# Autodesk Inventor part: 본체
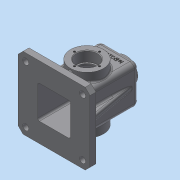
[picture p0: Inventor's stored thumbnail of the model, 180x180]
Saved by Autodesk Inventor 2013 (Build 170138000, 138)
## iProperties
Created: 2018-10
Part Number: 본체
Material: 일반
Document SubType Name: Modeling
Designer: Administrator
Density: 1 g/cm^3
Author: Administrator
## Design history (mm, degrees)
sketch "스케치1"
  geometry: L1 (-55, 32.5)-(55, 32.5); L2 (55, 32.5)-(55, -32.5); L3 (55, -32.5)-(-55, -32.5); L4 (-55, -32.5)-(-55, 32.5); L5 (-55, 32.5)-(55, -32.5); L6 (55, 32.5)-(-55, -32.5); 1 further point
  constraints: 12 end point, 2 midpoint, 2 parallel, 1 horizontal, 1 perpendicular
  dimensions: "d0" = 110 distance of L2.end L3.end; "d1" = 65 distance of L1.end L2.end
extrude "돌출1" new body sketch "스케치1" stored distance "d2" = 65; taper "d3" = 0 deg
fillet "모깎기1" dims "d4" = 8
fillet "모깎기2" dims "d5" = 8
feature "쉘1" dims "d6" = 5
sketch "스케치2"
  geometry: L1 (57, -8)-(57, -57) reference; L2 (0, 0)-(49, 0) reference; L3 (-8, -57)-(-8, -8) reference; L4 (49, -65)-(0, -65) reference; L5 (-35.5, -92.5)-(84.5, -92.5); L6 (84.5, -92.5)-(84.5, 27.5); L7 (84.5, 27.5)-(-35.5, 27.5); L8 (-35.5, 27.5)-(-35.5, -92.5); L9 (-35.5, -92.5)-(84.5, 27.5); L10 (84.5, -92.5)-(-35.5, 27.5); A1 r 8 centre (49, -57) between (49, -65) and (57, -57) reference; A2 r 8 centre (49, -8) between (57, -8) and (49, 0) reference; A3 r 8 centre (0, -8) between (0, 0) and (-8, -8) reference; A4 r 8 centre (0, -57) between (-8, -57) and (0, -65) reference; 1 further point
  constraints: 12 end point, 2 midpoint, 2 parallel, 1 horizontal, 1 perpendicular
  dimensions: "d7" = 120 distance of L7.end L6.end; "d8" = 120 distance of L6.end L5.end
extrude "돌출2" join sketch "스케치2" distance "d9" = 10; taper "d10" = 0 deg
chamfer "모따기1" distance "d11" = 8; stored, may be unused: second distance "d12" = 2, angle "d13" = 45 deg
sketch "스케치3"
  geometry: L1 (48, -45)-(35.218, 27.493); L2 (-24.5, 55)-(24.5, 55) reference; L3 (32.5, 47)-(32.5, -45) reference; L4 (32.5, -45)-(60, -45) reference; L5 (60, -45)-(60, -55) reference; L6 (60, -55)-(27.5, -55) reference; L7 (27.5, -55)-(27.5, 47) reference; L8 (24.5, 50)-(-24.5, 50) reference; L9 (-27.5, 47)-(-27.5, -55) reference; L10 (-27.5, -55)-(-60, -55) reference; L11 (-60, -55)-(-60, -45) reference; L12 (-60, -45)-(-32.5, -45) reference; L13 (-32.5, -45)-(-32.5, 47) reference; A1 r 8 centre (-24.5, 47) between (-24.5, 55) and (-32.5, 47) reference; A2 r 8 centre (24.5, 47) between (32.5, 47) and (24.5, 55) reference; A3 r 3 centre (24.5, 47) between (27.5, 47) and (24.5, 50) reference; A4 r 3 centre (-24.5, 47) between (-24.5, 50) and (-27.5, 47) reference; 1 further point
  constraints: 2 end point, 1 point on line
  dimensions: "d14" = 12 distance from line of L5 L1.start; "d15" = 10 deg angle of L5 L1
feature "리브1" sketch "스케치3" dims "d16" = 1, "d17" = 10, "d18" = 0, "d19" = 0, "d20" = 1, "d21" = 1
fillet "모깎기3" dims "d22" = 3
fillet "모깎기4" dims "d23" = 3
node "작업 평면1"
sketch "스케치4"
  geometry: C1 r 27.5 at (24.5, -47); 1 further point
  constraints: 1 centre point, 1 coincident
  dimensions: "d26" = 55 diameter of C1
extrude "돌출3" join sketch "스케치4" stored distance "d27" = 10; taper "d28" = 0 deg
hole "구멍1" diameter "d31" = 30; stored, may be unused: countersink angle "d35" = 90 deg, drill point angle "d37" = 118 deg; dims "d29" = 10, "d30" = 10, "d32" = 6, "d33" = 35, "d34" = 17, "d36" = 20
fillet "모깎기6" dims "d38" = 0.3
chamfer "모따기2" distance "d39" = 1; stored, may be unused: second distance "d40" = 2, angle "d41" = 45 deg
sketch "스케치5"
  geometry: L1 (0, 0)-(0, 21); C1 r 18.5 at (0, 0) reference
  constraints: 2 end point, 1 vertical
  dimensions: "d42" = 21 distance of L1.start L1.end
hole "구멍2" sketch "스케치5" at (0, 21) diameter "d43" = 3.459; stored, may be unused: countersink angle "d47" = 90 deg, drill point angle "d49" = 118 deg; dims "d44" = 8, "d45" = 35, "d46" = 17, "d48" = 10
sketch "스케치6"
  geometry: L1 (-55, 27.5)-(-55, 60) reference; L2 (-55, 60)-(-45, 60) reference; L3 (-45, 60)-(-45, 32.5) reference; L4 (-45, 32.5)-(-27.5, 32.5) reference; L5 (-27.5, 32.5)-(-27.5, 47.5) reference; L6 (-27.5, 47.5)-(-22.73, 47.5) reference; L7 (-22.73, 47.5)-(-22.73, 37.5) reference; L8 (-22.73, 37.5)-(-21, 36.461) reference; L9 (-21, 36.461)-(-19.271, 37.5) reference; L10 (-19.271, 37.5)-(-19.271, 47.5) reference; L11 (-19.271, 47.5)-(-18.5, 47.5) reference; L12 (-18.5, 47.5)-(-17.5, 46.5) reference; L13 (-17.5, 46.5)-(-17.5, 30.8) reference; L14 (-17.2, 30.5)-(-15, 30.5) reference; L15 (-15, 30.5)-(-15, 27.5) reference; L16 (-15, 27.5)-(-55, 27.5) reference; L17 (50, -24.5)-(50, 24.5) reference; L18 (47, 27.5)-(15, 27.5) reference; L19 (15, 27.5)-(15, 30.5) reference; L20 (15, 30.5)-(17.2, 30.5) reference; L21 (17.5, 30.8)-(17.5, 46.5) reference; L22 (17.5, 46.5)-(18.5, 47.5) reference; L23 (18.5, 47.5)-(19.271, 47.5) reference; L24 (19.271, 47.5)-(19.271, 37.5) reference; L25 (19.271, 37.5)-(21, 36.461) reference; L26 (21, 36.461)-(22.73, 37.5) reference; L27 (22.73, 37.5)-(22.73, 47.5) reference; L28 (22.73, 47.5)-(27.5, 47.5) reference; L29 (27.5, 47.5)-(27.5, 32.5) reference; L30 (27.5, 32.5)-(47, 32.5) reference; L31 (55, 24.5)-(55, -24.5) reference; L32 (47, -32.5)-(-45, -32.5) reference; L33 (-45, -32.5)-(-45, -60) reference; L34 (-45, -60)-(-55, -60) reference; L35 (-55, -60)-(-55, -27.5) reference; L36 (-55, -27.5)-(47, -27.5) reference; L37 (-45, 42.5)-(-31.143, 42.5); A1 r 0.3 centre (-17.2, 30.8) between (-17.5, 30.8) and (-17.2, 30.5) reference; A2 r 3 centre (47, 24.5) between (50, 24.5) and (47, 27.5) reference; A3 r 0.3 centre (17.2, 30.8) between (17.2, 30.5) and (17.5, 30.8) reference; A4 r 8 centre (47, 24.5) between (55, 24.5) and (47, 32.5) reference; A5 r 8 centre (47, -24.5) between (47, -32.5) and (55, -24.5) reference; A6 r 3 centre (47, -24.5) between (47, -27.5) and (50, -24.5) reference; 1 further point
  constraints: 2 end point, 1 parallel, 1 point on line
  dimensions: "d53" = 15 distance between parallel lines of L16 L37
feature "리브2" sketch "스케치6" dims "d54" = 1, "d55" = 6, "d56" = 0, "d57" = 0, "d58" = 1, "d59" = 1
fillet "모깎기7" dims "d60" = 3
fillet "모깎기9" dims "d62" = 3
fillet "모깎기10" dims "d63" = 3
fillet "모깎기11" dims "d64" = 1
fillet "모깎기12" dims "d65" = 3
node "작업 평면2"
sketch "스케치7"
  geometry: C1 r 20 at (0, 0); 1 further point
  constraints: 1 centre point, 1 coincident
  dimensions: "d67" = 40 diameter of C1
extrude "돌출4" join sketch "스케치7" stored distance "d68" = 10; taper "d69" = 7 deg
fillet "모깎기13" dims "d70" = 3
hole "구멍3" diameter "d73" = 22.835; stored, may be unused: countersink angle "d77" = 90 deg, drill point angle "d79" = 0 deg; dims "d71" = 10, "d72" = 10, "d74" = 20, "d75" = 35, "d76" = 17, "d78" = 10
chamfer "모따기3" distance "d80" = 1; stored, may be unused: second distance "d81" = 2, angle "d82" = 45 deg
sketch "스케치8"
  geometry: 2 further points
  dimensions: "d83" = 47.5 horizontal distance of point (4.5, -12.5) point (52, -60); "d84" = 47.5 horizontal distance of point (4.5, -12.5) point (52, -60)
hole "구멍4" sketch "스케치8" at (4.5, -12.5) diameter "d85" = 10; stored, may be unused: countersink angle "d89" = 90 deg, drill point angle "d91" = 0 deg; dims "d86" = 20, "d87" = 35, "d88" = 17, "d90" = 10
sketch "스케치9"
  geometry: L1 (-8, 0)-(-8, -91) reference; L2 (4.5, 18)-(44.5, 18) reference; 1 further point
  constraints: 1 other
  dimensions: "d98" = 32.5 distance from line of point (24.5, -8) L1; "d99" = 26 distance from line of L2 point (24.5, -8)
feature "엠보싱1" sketch "스케치9" dims "d100" = 0.5, "d101" = 0
node "솔리드1"
mirror "대칭1"
pattern_circular "원형 패턴1" dims angle "d51" = 360 deg
mirror "대칭2"
pattern_linear "직사각형 패턴1" dims "d94" = 95, "d97" = 95
node "절단 모서리 투영1"
node "절단 모서리 투영2"
other parameters: "d25" = 15, "d66" = 65
